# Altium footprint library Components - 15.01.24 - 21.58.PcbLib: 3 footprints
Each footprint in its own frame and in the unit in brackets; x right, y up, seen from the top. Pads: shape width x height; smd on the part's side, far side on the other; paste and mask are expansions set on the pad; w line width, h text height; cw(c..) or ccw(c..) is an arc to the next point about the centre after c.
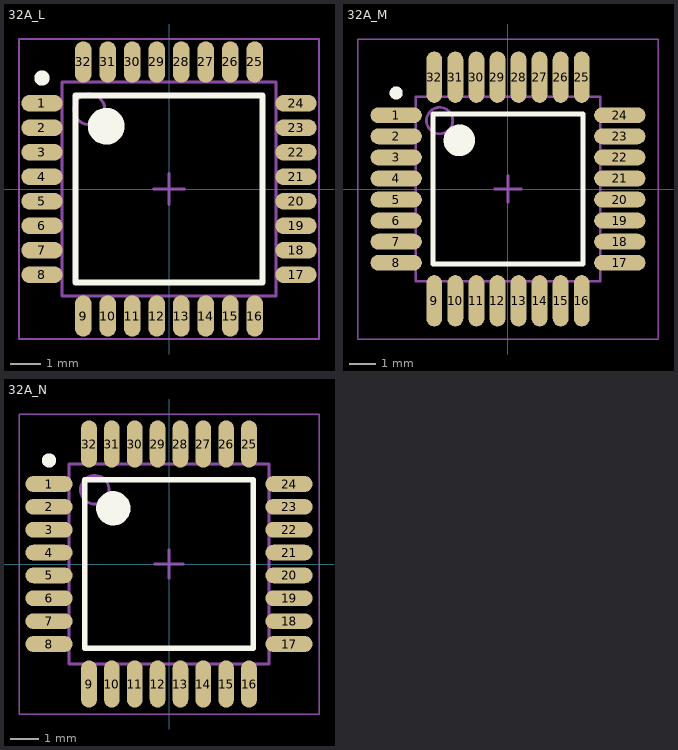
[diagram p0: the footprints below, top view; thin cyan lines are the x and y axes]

## 32A_L [mm] "Thin QFP, 32-Leads, Body 7x7mm, Pitch 0.8mm, IPC High Density"
height 1.2
pads (32):
  oval 1.35x0.55 smd: 1(-4.15,2.8) 2(-4.15,2) 3(-4.15,1.2) 4(-4.15,0.4) 5(-4.15,-0.4) 6(-4.15,-1.2) 7(-4.15,-2) 8(-4.15,-2.8) 17(4.15,-2.8) 18(4.15,-2) 19(4.15,-1.2) 20(4.15,-0.4) 21(4.15,0.4) 22(4.15,1.2) 23(4.15,2) 24(4.15,2.8)
  oval 0.55x1.35 smd: 9(-2.8,-4.15) 10(-2,-4.15) 11(-1.2,-4.15) 12(-0.4,-4.15) 13(0.4,-4.15) 14(1.2,-4.15) 15(2,-4.15) 16(2.8,-4.15) 25(2.8,4.15) 26(2,4.15) 27(1.2,4.15) 28(0.4,4.15) 29(-0.4,4.15) 30(-1.2,4.15) 31(-2,4.15) 32(-2.8,4.15)
Top Overlay:
  circle w0.25: c-4.15,3.625 r0.125
  circle w0.6: c-2.05,2.05 r0.3
  lines w0.2: -3.05,-3.05 -3.05,3.05 3.05,3.05 3.05,-3.05 -3.05,-3.05
Mechanical 13:
  circle w0.1: c-2.6,2.6 r0.5
  lines w0.1: -3.5,-3.5 -3.5,3.5 3.5,3.5 3.5,-3.5 -3.5,-3.5
Mechanical 15:
  lines w0.05: -4.9,-4.9 -4.9,4.9 4.9,4.9 4.9,-4.9 -4.9,-4.9
  lines w0.1: -0.5,0 0.5,0 ; 0,-0.5 0,0.5
3D body: height 1.2, standoff 0, extent -3.5,-3.5 3.5,3.5

## 32A_M [mm] "Thin QFP, 32-Leads, Body 7x7mm, Pitch 0.8mm, IPC Low Density"
height 1.2
pads (32):
  oval 1.95x0.6 smd: 1(-4.25,2.8) 2(-4.25,2) 3(-4.25,1.2) 4(-4.25,0.4) 5(-4.25,-0.4) 6(-4.25,-1.2) 7(-4.25,-2) 8(-4.25,-2.8) 17(4.25,-2.8) 18(4.25,-2) 19(4.25,-1.2) 20(4.25,-0.4) 21(4.25,0.4) 22(4.25,1.2) 23(4.25,2) 24(4.25,2.8)
  oval 0.6x1.95 smd: 9(-2.8,-4.25) 10(-2,-4.25) 11(-1.2,-4.25) 12(-0.4,-4.25) 13(0.4,-4.25) 14(1.2,-4.25) 15(2,-4.25) 16(2.8,-4.25) 25(2.8,4.25) 26(2,4.25) 27(1.2,4.25) 28(0.4,4.25) 29(-0.4,4.25) 30(-1.2,4.25) 31(-2,4.25) 32(-2.8,4.25)
Top Overlay:
  circle w0.25: c-4.25,3.65 r0.125
  circle w0.6: c-1.85,1.85 r0.3
  lines w0.2: -2.85,-2.85 -2.85,2.85 2.85,2.85 2.85,-2.85 -2.85,-2.85
Mechanical 13:
  circle w0.1: c-2.6,2.6 r0.5
  lines w0.1: -3.5,-3.5 -3.5,3.5 3.5,3.5 3.5,-3.5 -3.5,-3.5
Mechanical 15:
  lines w0.05: -5.7,-5.7 -5.7,5.7 5.7,5.7 5.7,-5.7 -5.7,-5.7
  lines w0.1: -0.5,0 0.5,0 ; 0,-0.5 0,0.5
3D body: height 1.2, standoff 0, extent -3.5,-3.5 3.5,3.5

## 32A_N [mm] "Thin QFP, 32-Leads, Body 7x7mm, Pitch 0.8mm, IPC Medium Density"
height 1.2
pads (32):
  oval 1.65x0.55 smd: 1(-4.2,2.8) 2(-4.2,2) 3(-4.2,1.2) 4(-4.2,0.4) 5(-4.2,-0.4) 6(-4.2,-1.2) 7(-4.2,-2) 8(-4.2,-2.8) 17(4.2,-2.8) 18(4.2,-2) 19(4.2,-1.2) 20(4.2,-0.4) 21(4.2,0.4) 22(4.2,1.2) 23(4.2,2) 24(4.2,2.8)
  oval 0.55x1.65 smd: 9(-2.8,-4.2) 10(-2,-4.2) 11(-1.2,-4.2) 12(-0.4,-4.2) 13(0.4,-4.2) 14(1.2,-4.2) 15(2,-4.2) 16(2.8,-4.2) 25(2.8,4.2) 26(2,4.2) 27(1.2,4.2) 28(0.4,4.2) 29(-0.4,4.2) 30(-1.2,4.2) 31(-2,4.2) 32(-2.8,4.2)
Top Overlay:
  circle w0.6: c-1.95,1.95 r0.3
  circle w0.25: c-4.2,3.625 r0.125
  lines w0.2: -2.95,-2.95 2.95,-2.95 2.95,2.95 -2.95,2.95 -2.95,-2.95
Mechanical 13:
  circle w0.1: c-2.6,2.6 r0.5
  lines w0.1: -3.5,-3.5 3.5,-3.5 3.5,3.5 -3.5,3.5 -3.5,-3.5
Mechanical 15:
  lines w0.05: -5.25,-5.25 5.25,-5.25 5.25,5.25 -5.25,5.25 -5.25,-5.25
  lines w0.1: -0.5,0 0.5,0 ; 0,-0.5 0,0.5
3D body: height 1.2, standoff 0, extent -3.5,-3.5 3.5,3.5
